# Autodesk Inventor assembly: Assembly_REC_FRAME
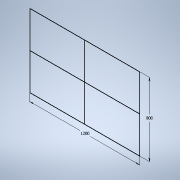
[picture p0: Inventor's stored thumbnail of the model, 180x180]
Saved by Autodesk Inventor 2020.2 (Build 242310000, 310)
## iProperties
Created: 2020-01
Part Number: Assembly_REC_FRAME
Document SubType Name: Assembly
Designer: thira
Author: thira
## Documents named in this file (2)
- F:\99.โปรแกรมอัดหน้าจอ\Synergysoft\FRAME\Frame_Generator\Frame\Assembly_REC_FRAME.iam
- F:\99.โปรแกรมอัดหน้าจอ\Synergysoft\FRAME\Structure.ipt
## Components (1 placed, 1 different names)
1. Structure:1
